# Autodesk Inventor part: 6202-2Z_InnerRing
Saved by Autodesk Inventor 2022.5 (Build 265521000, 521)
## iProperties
Created: 2024-12
Part Number: 6202-2Z_InnerRing
Material: Generic
Document SubType Name: Modeling
Designer: AdminForWorker
Density: 1 g/cm^3
Appearance: Default
Title: 6202-2Z_InnerRing
Author: AdminForWorker
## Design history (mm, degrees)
feature "Body1"
body "Solid1"
